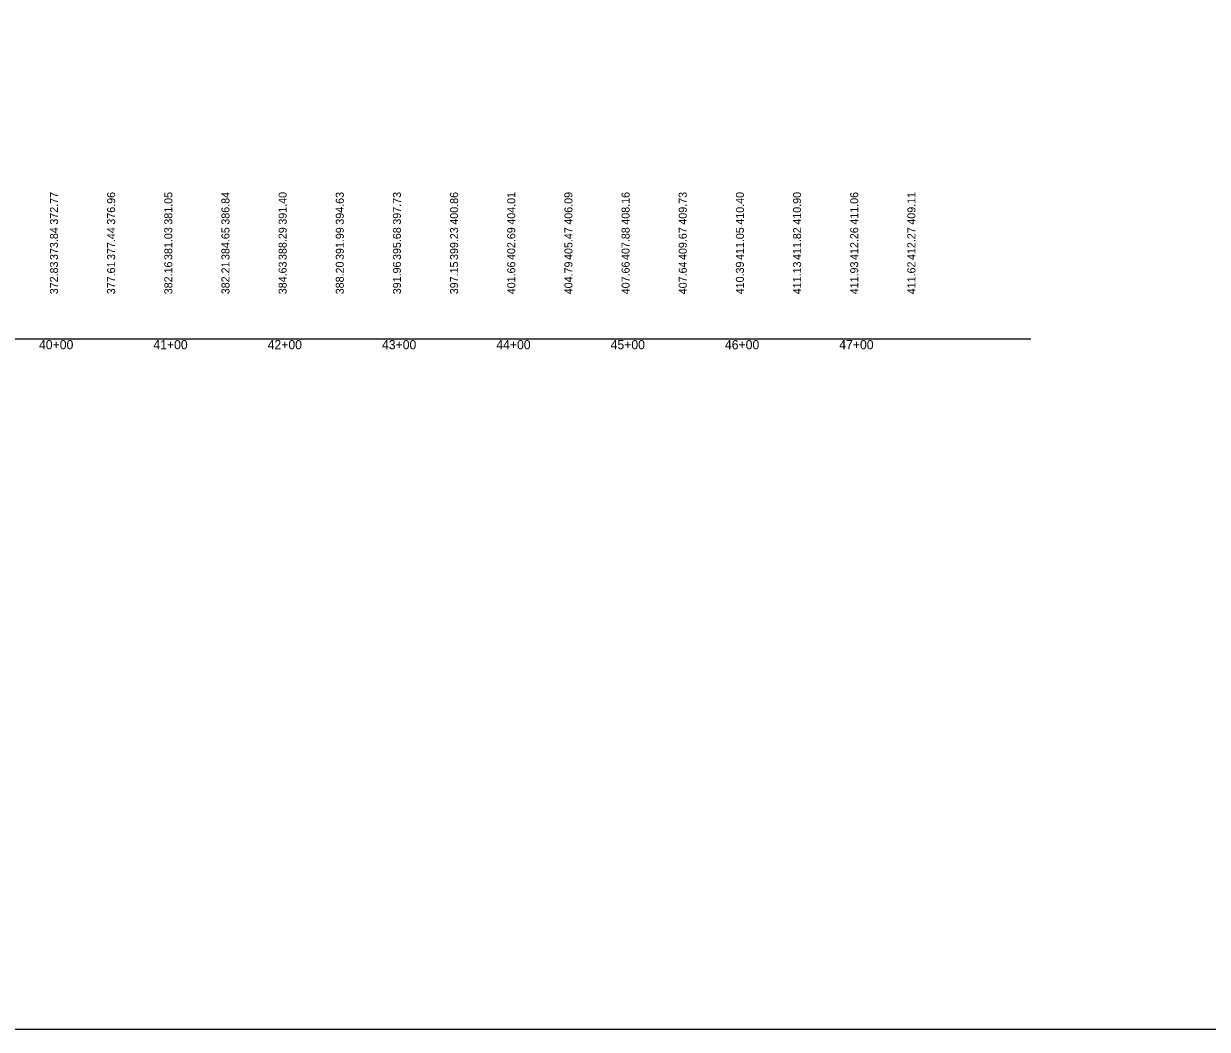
# Model space of a CAD drawing. Extents: x 2005261 to 2010661, y 1001568 to 1006764.
# Drawn here: x 2008591 to 2009626, y 1003464 to 1004344 of the extents above; entities that cross this region are included whole.
import ezdxf

# ---------------------------------------------------------------- set-up
doc = ezdxf.new("R2010")
doc.units = 0
for name, color, linetype in [('RD_DDB_StaTX', 7, 'Continuous'), ('RD_DDB_StripGrade', 7, 'Continuous'), ('RD_GPK_Profile_Cell', 7, 'Continuous'), ('RD_Sketch2', 7, 'Continuous'), ('RD_Sketch3', 7, 'Continuous'), ('RD_Sketch4', 7, 'Continuous')]:
    doc.layers.add(name, color=color, linetype=linetype)

msp = doc.modelspace()

# ---------------------------------------------------------------- linework, layer by layer
at = {"layer": 'RD_GPK_Profile_Cell'}
msp.add_line((2006171.7, 1004068.4), (2009471.7, 1004068.4), dxfattribs=at)
at = {"layer": 'RD_Sketch4'}
msp.add_lwpolyline([(2005261.5, 1006764.3), (2010661.5, 1006764.3), (2010661.5, 1003464.3), (2005261.5, 1003464.3)], close=True, dxfattribs=at)

# ---------------------------------------------------------------- texts
at = {"layer": 'RD_DDB_StaTX'}
for s, p in [('40+00', (2008604.1, 1004059.4)), ('41+00', (2008704.1, 1004059.4)), ('42+00', (2008804.1, 1004059.4)), ('43+00', (2008904.1, 1004059.4)), ('44+00', (2009004.1, 1004059.4)), ('45+00', (2009104.1, 1004059.4)), ('46+00', (2009204.1, 1004059.4)), ('47+00', (2009304.1, 1004059.4))]:
    msp.add_text(s, height=8, dxfattribs=at).set_placement(p)
at = {"layer": 'RD_DDB_StripGrade'}
for s, p in [('373.84', (2008620.7, 1004137.5)), ('377.44', (2008670.7, 1004137.5)), ('381.03', (2008720.7, 1004137.5)), ('384.65', (2008770.7, 1004137.5)), ('388.29', (2008820.7, 1004137.5)), ('391.99', (2008870.7, 1004137.5)), ('395.68', (2008920.7, 1004137.5)), ('399.23', (2008970.7, 1004137.5)), ('402.69', (2009020.7, 1004137.5)), ('405.47', (2009070.7, 1004137.5)), ('407.88', (2009120.7, 1004137.5)), ('409.67', (2009170.7, 1004137.5)), ('411.05', (2009220.7, 1004137.5)), ('411.82', (2009270.7, 1004137.5)), ('412.26', (2009320.7, 1004137.5)), ('412.27', (2009370.7, 1004137.5))]:
    msp.add_text(s, height=7, rotation=90, dxfattribs=at).set_placement(p)
at = {"layer": 'RD_Sketch2'}
for s, p in [('372.83', (2008620.7, 1004107.5)), ('377.61', (2008670.7, 1004107.5)), ('382.16', (2008720.7, 1004107.5)), ('382.21', (2008770.7, 1004107.5)), ('384.63', (2008820.7, 1004107.5)), ('388.20', (2008870.7, 1004107.5)), ('391.96', (2008920.7, 1004107.5)), ('397.15', (2008970.7, 1004107.5)), ('401.66', (2009020.7, 1004107.5)), ('404.79', (2009070.7, 1004107.5)), ('407.66', (2009120.7, 1004107.5)), ('407.64', (2009170.7, 1004107.5)), ('410.39', (2009220.7, 1004107.5)), ('411.13', (2009270.7, 1004107.5)), ('411.93', (2009320.7, 1004107.5)), ('411.62', (2009370.7, 1004107.5))]:
    msp.add_text(s, height=7, rotation=90, dxfattribs=at).set_placement(p)
at = {"layer": 'RD_Sketch3'}
for s, p in [('372.77', (2008620.7, 1004168.4)), ('376.96', (2008670.7, 1004168.4)), ('381.05', (2008720.7, 1004168.4)), ('386.84', (2008770.7, 1004168.4)), ('391.40', (2008820.7, 1004168.4)), ('394.63', (2008870.7, 1004168.4)), ('397.73', (2008920.7, 1004168.4)), ('400.86', (2008970.7, 1004168.4)), ('404.01', (2009020.7, 1004168.4)), ('406.09', (2009070.7, 1004168.4)), ('408.16', (2009120.7, 1004168.4)), ('409.73', (2009170.7, 1004168.4)), ('410.40', (2009220.7, 1004168.4)), ('410.90', (2009270.7, 1004168.4)), ('411.06', (2009320.7, 1004168.4)), ('409.11', (2009370.7, 1004168.4))]:
    msp.add_text(s, height=7, rotation=90, dxfattribs=at).set_placement(p)

doc.saveas('drawing.dxf')
